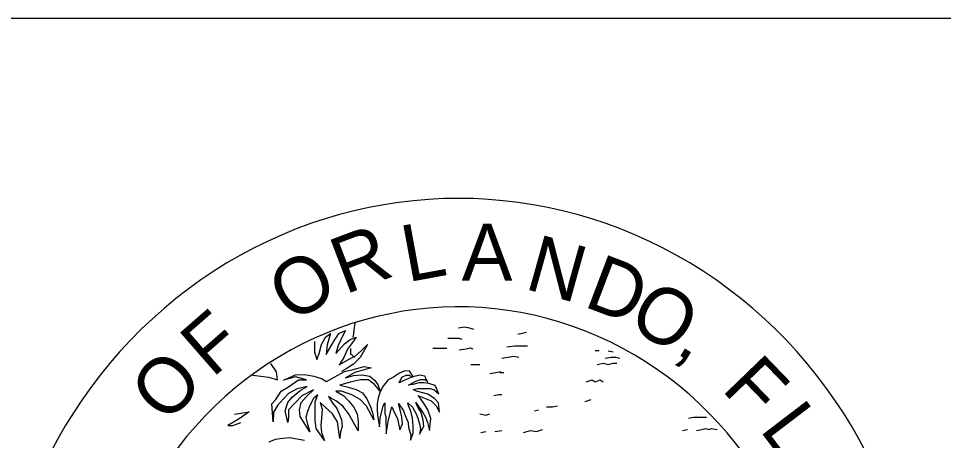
# Model space of a CAD drawing. Extents: x 29.7 to 46.4, y -39.2 to -28.2.
# Drawn here: x 42.087 to 42.83, y -37.805 to -37.466 of the extents above; entities that cross this region are included whole.
import ezdxf

# ---------------------------------------------------------------- set-up
doc = ezdxf.new("R2010")
doc.units = 0
doc.layers.add('Level 60', color=7, linetype='Continuous')

msp = doc.modelspace()

# ---------------------------------------------------------------- linework, layer by layer
at = {"layer": 'Level 60'}
for p, q in [((42.48832, -37.71947), (42.49547, -37.71782)), ((42.35369, -37.7347), (42.35721, -37.73807)), ((42.35402, -37.73075), (42.35402, -37.73571)), ((42.55374, -37.73278), (42.55052, -37.73278)), ((42.56092, -37.73278), (42.56491, -37.73364)), ((42.47396, -37.75025), (42.47711, -37.75025)), ((42.54253, -37.77355), (42.5473, -37.77185)), ((42.50182, -37.781), (42.50505, -37.78015)), ((42.45876, -37.79846), (42.46273, -37.79761)), ((42.46993, -37.79761), (42.4755, -37.79678)), ((42.62074, -37.79678), (42.62474, -37.79596))]:
    msp.add_line(p, q, dxfattribs=at)
for points in [[(45.78223, -37.46558), (41.92298, -37.46558)], [(42.35739, -37.71054), (42.35671, -37.71581), (42.35602, -37.72103), (42.35561, -37.72209)], [(42.44083, -37.71436), (42.4456, -37.71354), (42.44961, -37.71436), (42.45279, -37.7152)], [(42.32505, -37.72513), (42.32505, -37.7338), (42.32686, -37.73958), (42.32872, -37.73479), (42.33056, -37.72753), (42.33388, -37.72172), (42.338, -37.71883), (42.33523, -37.72801), (42.33428, -37.73571), (42.34029, -37.72561), (42.34449, -37.71883), (42.35003, -37.71641), (42.34771, -37.7203), (42.34402, -37.72853), (42.34219, -37.73479), (42.34913, -37.72701), (42.35371, -37.72364), (42.35839, -37.72172), (42.35464, -37.72701), (42.35144, -37.73139), (42.34863, -37.73817), (42.34496, -37.74389), (42.35188, -37.74006), (42.35791, -37.73668), (42.36253, -37.7328), (42.36767, -37.72753), (42.3616, -37.73817), (42.35649, -37.74344), (42.3505, -37.74729), (42.34676, -37.74923)], [(42.43218, -37.72245), (42.4385, -37.72245), (42.44093, -37.72245), (42.44333, -37.72328)], [(42.4795, -37.72952), (42.48588, -37.72863), (42.49067, -37.72863), (42.49624, -37.72863)], [(42.4202, -37.73056), (42.42572, -37.73056), (42.42733, -37.73056), (42.4313, -37.73056)], [(42.44121, -37.73193), (42.44678, -37.73113), (42.45, -37.73027), (42.45236, -37.73113)], [(42.27364, -37.75206), (42.28799, -37.754), (42.2954, -37.75592), (42.29448, -37.74966), (42.28983, -37.74292)], [(42.45075, -37.7436), (42.45472, -37.7436), (42.45795, -37.7436)], [(42.4755, -37.73861), (42.48029, -37.73777), (42.48513, -37.73697), (42.4891, -37.73777)], [(42.55211, -37.7436), (42.55693, -37.74278), (42.56092, -37.7436), (42.56491, -37.74278), (42.56806, -37.74278)], [(42.5585, -37.73861), (42.56329, -37.73777), (42.56724, -37.73777), (42.57048, -37.73861)], [(42.29213, -37.78201), (42.29188, -37.78993), (42.29078, -37.77528), (42.29401, -37.77192), (42.29815, -37.76514), (42.30416, -37.76176), (42.31205, -37.75604), (42.31856, -37.75604), (42.30973, -37.75355), (42.30002, -37.75642), (42.30973, -37.75214), (42.31714, -37.75167), (42.32455, -37.75308), (42.33056, -37.75504), (42.33474, -37.75741), (42.34125, -37.75355), (42.34913, -37.74923), (42.35602, -37.74776), (42.36482, -37.74541), (42.37044, -37.74632), (42.35746, -37.75016), (42.35003, -37.75452), (42.35649, -37.75264), (42.36296, -37.75214), (42.36947, -37.75308), (42.37316, -37.75642), (42.37599, -37.75982), (42.3778, -37.76514), (42.37316, -37.75982), (42.36854, -37.75604), (42.36205, -37.75604), (42.35371, -37.75793), (42.34539, -37.76031), (42.35096, -37.76176), (42.35839, -37.7637), (42.36346, -37.76655), (42.36717, -37.7714), (42.36996, -37.77767), (42.37179, -37.78348), (42.37274, -37.78828), (42.36671, -37.77719), (42.3616, -37.77192), (42.35514, -37.76802), (42.34676, -37.76514), (42.34219, -37.76514), (42.34863, -37.76901), (42.35234, -37.77286), (42.35649, -37.77767), (42.35933, -37.78348), (42.36022, -37.78927), (42.36022, -37.79698), (42.35602, -37.78974), (42.35234, -37.78298), (42.34771, -37.77719), (42.34261, -37.77329), (42.338, -37.77043), (42.33615, -37.76951), (42.3394, -37.77478), (42.34261, -37.77866), (42.34496, -37.78348), (42.34676, -37.78828), (42.34728, -37.79357), (42.34585, -37.79795), (42.34539, -37.80326), (42.34354, -37.78974), (42.3394, -37.78348), (42.33335, -37.77767), (42.32966, -37.77428), (42.33106, -37.77963), (42.33056, -37.78685), (42.33014, -37.79263), (42.33056, -37.79844), (42.33293, -37.80471), (42.3264, -37.79506), (42.32546, -37.78879), (42.32546, -37.78057), (42.32546, -37.77381), (42.32781, -37.76802), (42.32409, -37.77093), (42.3213, -37.7767), (42.31946, -37.78152), (42.31808, -37.78639), (42.31946, -37.79168), (42.3213, -37.79795), (42.31346, -37.78542), (42.31298, -37.78007), (42.31434, -37.77428), (42.31856, -37.76951), (42.32409, -37.76419), (42.31484, -37.76901), (42.30973, -37.77428), (42.30416, -37.78007), (42.30416, -37.78589), (42.30372, -37.79024), (42.30141, -37.78109), (42.30372, -37.77428), (42.30695, -37.76994), (42.31346, -37.76465), (42.31903, -37.76131), (42.31115, -37.7632)], [(42.37576, -37.78482), (42.37721, -37.79383), (42.3778, -37.78689), (42.38017, -37.77707), (42.38148, -37.77464), (42.38148, -37.77707), (42.38148, -37.77986), (42.38148, -37.78301), (42.38221, -37.78584), (42.38252, -37.7995), (42.38454, -37.78828), (42.3872, -37.7778), (42.38824, -37.78024), (42.3899, -37.78372), (42.3916, -37.78726), (42.39259, -37.79109), (42.39365, -37.79636), (42.39565, -37.79145), (42.39529, -37.78618), (42.39396, -37.78024), (42.39259, -37.77495), (42.39664, -37.78093), (42.39799, -37.78482), (42.40035, -37.79035), (42.40068, -37.79423), (42.40235, -37.80021), (42.40203, -37.80442), (42.40443, -37.79879), (42.40443, -37.79319), (42.40371, -37.78689), (42.40235, -37.78128), (42.40068, -37.77707), (42.39999, -37.77464), (42.40371, -37.77809), (42.40675, -37.78336), (42.40807, -37.78689), (42.40944, -37.79145), (42.41007, -37.79534), (42.40944, -37.79985), (42.41283, -37.79319), (42.41246, -37.7886), (42.41079, -37.78229), (42.40807, -37.77809), (42.4064, -37.77426), (42.41211, -37.78229), (42.41414, -37.78618), (42.41578, -37.79035), (42.41753, -37.79669), (42.41851, -37.78726), (42.41618, -37.78024), (42.41381, -37.77603), (42.41007, -37.77111), (42.40807, -37.76869), (42.41479, -37.77145), (42.41885, -37.77292), (42.42286, -37.77707), (42.42556, -37.78199), (42.42454, -37.77464), (42.42155, -37.77111), (42.41618, -37.76759), (42.40705, -37.76514), (42.40443, -37.76377), (42.40807, -37.76306), (42.41314, -37.76306), (42.41783, -37.76306), (42.42119, -37.76413), (42.42489, -37.76729), (42.4219, -37.76063), (42.41685, -37.75888), (42.41283, -37.7585), (42.40909, -37.7585), (42.40401, -37.75989), (42.40068, -37.76022), (42.4064, -37.75713), (42.41007, -37.75571), (42.41381, -37.75571), (42.41618, -37.75779), (42.41381, -37.75323), (42.40975, -37.75221), (42.40401, -37.75358), (42.39864, -37.75571), (42.39565, -37.75713), (42.39292, -37.7585), (42.39529, -37.754), (42.39864, -37.75221), (42.40135, -37.75221), (42.4027, -37.75358), (42.40303, -37.754), (42.40443, -37.75358), (42.40135, -37.74871), (42.39696, -37.74904), (42.3933, -37.75081), (42.3886, -37.754), (42.38419, -37.75606), (42.37982, -37.76131), (42.37748, -37.76655), (42.37608, -37.77043), (42.37545, -37.77534), (42.37545, -37.77953), (42.37576, -37.78482)], [(42.46596, -37.75103), (42.47074, -37.75025), (42.47471, -37.74942)], [(42.54332, -37.75776), (42.54811, -37.75606), (42.55052, -37.75776), (42.55449, -37.75606), (42.55693, -37.75776)], [(42.31115, -37.7632), (42.30416, -37.76703), (42.30002, -37.7714), (42.2954, -37.7767), (42.29213, -37.78201)], [(42.46911, -37.76854), (42.4731, -37.76772), (42.4755, -37.76772)], [(42.51145, -37.77767), (42.51621, -37.77767), (42.52019, -37.77683)], [(42.26083, -37.78355), (42.27242, -37.78164), (42.26451, -37.78743), (42.25527, -37.79272), (42.25946, -37.79272), (42.26595, -37.79031)], [(42.45795, -37.7835), (42.46273, -37.78433), (42.46596, -37.7835)], [(42.62553, -37.78683), (42.62948, -37.78601), (42.63352, -37.78601), (42.63591, -37.78601), (42.63988, -37.78601)], [(42.63196, -37.79678), (42.63591, -37.79596), (42.6391, -37.7951), (42.64228, -37.79596), (42.64386, -37.7951), (42.64868, -37.79596)], [(42.31706, -37.80486), (42.30495, -37.80272), (42.29952, -37.80333), (42.29338, -37.80397), (42.28833, -37.80626)], [(42.49304, -37.79846), (42.49863, -37.79678), (42.50345, -37.79761), (42.50821, -37.79596)]]:
    msp.add_lwpolyline(points, dxfattribs=at)
for major_axis, start_param, end_param in [((0, 0.38741), 4.712389, 7.853982), ((0, -0.30024), 1.556924, 6.293762)]:
    msp.add_ellipse((42.44065, -37.99761), major_axis=major_axis, ratio=0.96, start_param=start_param, end_param=end_param, dxfattribs=at)

# ---------------------------------------------------------------- texts
for s, height, rotation, p in [('L', 0.04559, 10.40774, (42.39976, -37.67764)), ('R', 0.04543, 20.76351, (42.3494, -37.68769)), ('N', 0.04552, 344.40485, (42.49284, -37.6826)), ('O', 0.04519, 31.02297, (42.3063, -37.71118)), ('D', 0.04543, 339.23649, (42.54022, -37.69667)), ('O', 0.04519, 328.97703, (42.57507, -37.71213)), ('F', 0.04489, 41.15548, (42.2429, -37.75509)), (',', 0.04519, 328.97703, (42.61421, -37.73396)), ('F', 0.04474, 314.01965, (42.65126, -37.76391)), ('O', 0.04474, 46.16914, (42.20568, -37.79251)), ('L', 0.04453, 307.34313, (42.68207, -37.79607))]:
    msp.add_text(s, height=height, rotation=rotation, dxfattribs=at).set_placement(p)
msp.add_text('A', height=0.04564, dxfattribs=at).set_placement((42.44333, -37.67624))

doc.saveas('drawing.dxf')
